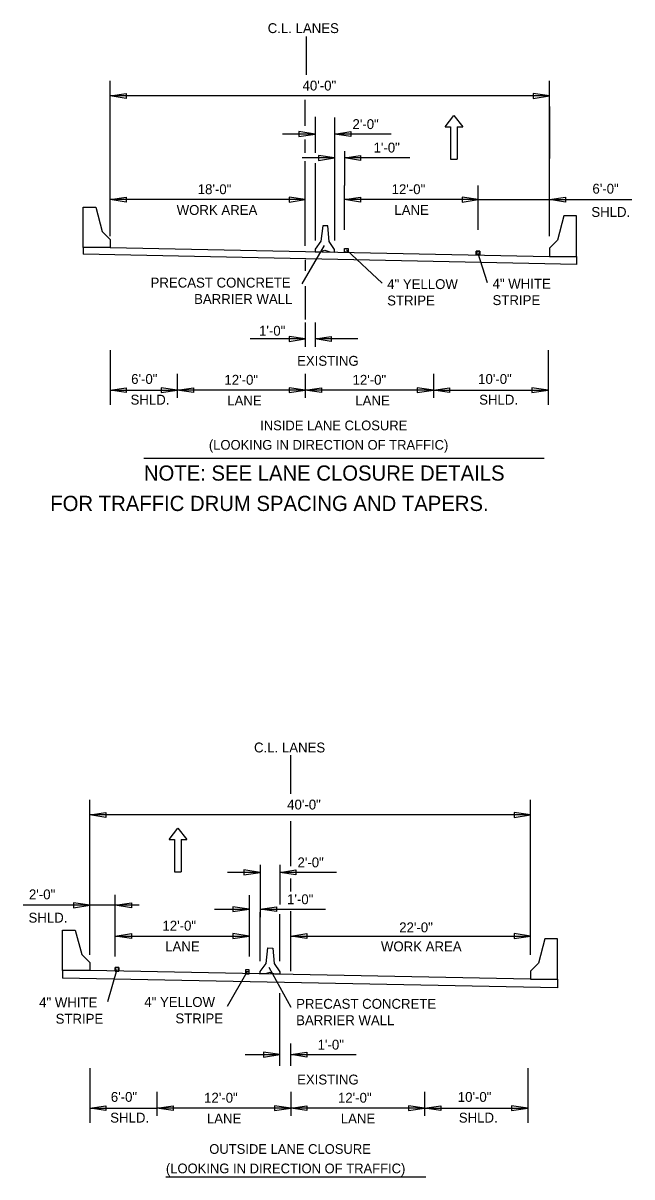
# Model space of a CAD drawing. Extents: x 13528 to 25043, y 7635 to 10612.
# Drawn here: x 24667 to 25043, y 9711 to 10423 of the extents above; entities that cross this region are included whole.
import ezdxf

# ---------------------------------------------------------------- set-up
doc = ezdxf.new("R2010")
doc.units = 0
for name, color, linetype in [('Default', 7, 'Continuous'), ('STAMP_PE_TAEGTMEYER-SIGNATURE', 7, 'Continuous'), ('STAMP_PRELIMINARY', 7, 'Continuous')]:
    doc.layers.add(name, color=color, linetype=linetype)

msp = doc.modelspace()

# ---------------------------------------------------------------- linework, layer by layer
at = {"layer": 'Default'}
for p, q in [((24841.84, 10391.32), (24841.84, 10415.16)), ((24720.38, 10291.82), (24720.38, 10387.65)), ((24991.93, 10291.82), (24991.93, 10387.65)), ((24991.93, 10378.33), (24720.38, 10378.33)), ((24841.04, 10359.8), (24841.04, 10376)), ((24991.93, 10371.84), (24991.93, 10339.74)), ((24847.12, 10365.43), (24847.12, 10343.14)), ((24859.18, 10365.07), (24859.18, 10332.97)), ((24847.12, 10354.79), (24826.95, 10354.79)), ((24841.04, 10343.26), (24841.04, 10351.36)), ((24894.21, 10354.79), (24859.18, 10354.79)), ((24865.21, 10344.18), (24865.21, 10323.08)), ((24859.18, 10340.02), (24839.02, 10340.02)), ((24841.04, 10324.57), (24841.04, 10337.97)), ((24847.12, 10336.78), (24847.12, 10305.87)), ((24905.59, 10340.02), (24865.21, 10340.02)), ((24859.18, 10332.97), (24859.18, 10288.96)), ((24841.04, 10285.69), (24841.04, 10324.57)), ((24865.21, 10295.57), (24865.21, 10323.08)), ((24947.95, 10295.57), (24947.95, 10323.08)), ((24841.04, 10314.31), (24720.38, 10314.31)), ((24947.95, 10314.31), (24865.21, 10314.31)), ((24947.95, 10314.31), (25042.91, 10314.31)), ((24847.12, 10305.87), (24847.12, 10288.96)), ((24839.18, 10262.21), (24852.93, 10285.86)), ((24865.21, 10281.75), (24865.21, 10284.04)), ((24865.21, 10284.04), (24867.51, 10284.04)), ((24865.21, 10281.75), (24865.21, 10284.04)), ((24865.21, 10284.04), (24867.51, 10284.04)), ((24867.51, 10281.75), (24865.21, 10281.75)), ((24888.49, 10262.67), (24866.4, 10283.19)), ((24867.51, 10284.04), (24867.51, 10281.75)), ((24867.51, 10284.04), (24867.51, 10281.75)), ((24948.92, 10282.42), (24946.62, 10282.42)), ((24946.62, 10282.42), (24946.62, 10280.12)), ((24946.62, 10280.12), (24946.62, 10282.42)), ((24946.62, 10282.42), (24948.92, 10282.42)), ((24948.92, 10280.12), (24946.62, 10280.12)), ((24953.62, 10262.9), (24947.77, 10281.55)), ((24948.92, 10280.12), (24948.92, 10282.42)), ((24948.92, 10282.42), (24948.92, 10280.12)), ((24841.04, 10277.11), (24841.04, 10270.29)), ((24841.04, 10260.9), (24841.04, 10240.29)), ((24841.04, 10238.38), (24841.04, 10223.42)), ((24847.07, 10238.38), (24847.07, 10223.42)), ((24841.04, 10228.22), (24806.88, 10228.22)), ((24873.44, 10228.22), (24847.07, 10228.22)), ((24720.38, 10221.33), (24720.38, 10187.46)), ((24991.14, 10221.33), (24991.14, 10187.46)), ((24720.38, 10206.74), (24720.38, 10191.78)), ((24761.88, 10206.74), (24761.88, 10191.78)), ((24841.04, 10206.74), (24841.04, 10191.78)), ((24920.2, 10206.74), (24920.2, 10191.78)), ((24720.38, 10196.58), (24761.88, 10196.58)), ((24841.04, 10196.58), (24761.88, 10196.58)), ((24920.2, 10196.58), (24841.04, 10196.58)), ((24920.2, 10196.58), (24991.14, 10196.58)), ((24741.33, 10154.6), (24988.59, 10154.6)), ((24832.05, 9947.17), (24832.05, 9971.01)), ((24707.81, 9847.68), (24707.81, 9943.51)), ((24980.16, 9847.68), (24980.16, 9943.51)), ((24980.16, 9934.18), (24707.81, 9934.18)), ((24832.05, 9902.56), (24832.05, 9930.28)), ((24813.15, 9903.43), (24813.15, 9871.02)), ((24825.21, 9903.43), (24825.21, 9878.94)), ((24813.15, 9898.71), (24792.98, 9898.71)), ((24860.24, 9898.71), (24825.21, 9898.71)), ((24832.05, 9886.93), (24832.05, 9894.85)), ((24723.57, 9846.66), (24723.57, 9884.83)), ((24806.3, 9884.72), (24806.3, 9846.66)), ((24738.35, 9878.37), (24666.6, 9878.37)), ((24784.95, 9875.95), (24806.3, 9875.95)), ((24813.14, 9875.95), (24853.48, 9875.95)), ((24813.14, 9843.86), (24813.14, 9874.18)), ((24825.21, 9843.86), (24825.21, 9872.93)), ((24832.05, 9847.85), (24832.05, 9874.69)), ((24723.57, 9859.37), (24806.3, 9859.37)), ((24832.05, 9859.37), (24980.16, 9859.37)), ((24832.05, 9837.77), (24832.05, 9847.85)), ((24718.91, 9818.98), (24724.71, 9838.88)), ((24723.57, 9837.74), (24723.57, 9840.03)), ((24723.57, 9840.03), (24725.86, 9840.03)), ((24725.86, 9840.03), (24723.57, 9840.03)), ((24723.57, 9840.03), (24723.57, 9837.74)), ((24723.57, 9837.74), (24725.86, 9837.74)), ((24725.86, 9840.03), (24725.86, 9837.74)), ((24725.86, 9837.74), (24725.86, 9840.03)), ((24792.92, 9816.05), (24805.16, 9837.28)), ((24804.01, 9838.43), (24804.01, 9836.13)), ((24806.3, 9838.43), (24804.01, 9838.43)), ((24804.01, 9838.43), (24804.01, 9836.13)), ((24806.3, 9837.28), (24804.01, 9837.28)), ((24806.3, 9836.13), (24806.3, 9838.43)), ((24806.3, 9836.13), (24806.3, 9838.43)), ((24832.22, 9815.19), (24818.79, 9839.88)), ((24804.01, 9836.13), (24806.3, 9836.13)), ((24825.21, 9779.25), (24825.21, 9824.16)), ((24832.05, 9779.25), (24832.05, 9793.01)), ((24803.86, 9786.13), (24825.21, 9786.13)), ((24832.05, 9786.13), (24872.38, 9786.13)), ((24707.81, 9777.82), (24707.81, 9743.95)), ((24978.56, 9777.82), (24978.56, 9743.95)), ((24707.81, 9763.23), (24707.81, 9748.27)), ((24749.31, 9763.23), (24749.31, 9748.27)), ((24832.05, 9763.23), (24832.05, 9748.27)), ((24914.79, 9763.23), (24914.79, 9748.27)), ((24707.81, 9753.07), (24749.31, 9753.07)), ((24832.05, 9753.07), (24749.31, 9753.07)), ((24914.79, 9753.07), (24832.05, 9753.07)), ((24914.79, 9753.07), (24978.56, 9753.07)), ((24754.87, 9710.57), (24915.46, 9710.57))]:
    msp.add_line(p, q, dxfattribs=at)
for points in [[(24720.38, 10378.33), (24730.38, 10379.83), (24730.38, 10376.83)], [(24991.93, 10378.33), (24981.93, 10379.83), (24981.93, 10376.83)], [(24847.12, 10354.79), (24837.12, 10356.29), (24837.12, 10353.29)], [(24859.18, 10354.79), (24869.18, 10356.29), (24869.18, 10353.29)], [(24859.18, 10340.02), (24849.18, 10341.52), (24849.18, 10338.52)], [(24865.21, 10340.02), (24875.21, 10341.52), (24875.21, 10338.52)], [(24720.38, 10314.31), (24730.38, 10315.81), (24730.38, 10312.81)], [(24841.04, 10314.31), (24831.04, 10315.81), (24831.04, 10312.81)], [(24865.21, 10314.31), (24875.21, 10315.81), (24875.21, 10312.81)], [(24947.95, 10314.31), (24937.95, 10315.81), (24937.95, 10312.81)], [(24991.93, 10314.31), (25001.93, 10315.81), (25001.93, 10312.81)], [(24841.04, 10228.22), (24831.04, 10229.72), (24831.04, 10226.72)], [(24847.07, 10228.22), (24857.07, 10229.72), (24857.07, 10226.72)], [(24720.38, 10196.58), (24730.38, 10198.08), (24730.38, 10195.08)], [(24761.88, 10196.58), (24751.88, 10198.08), (24751.88, 10195.08)], [(24761.88, 10196.58), (24771.88, 10198.08), (24771.88, 10195.08)], [(24841.04, 10196.58), (24831.04, 10198.08), (24831.04, 10195.08)], [(24841.04, 10196.58), (24851.04, 10198.08), (24851.04, 10195.08)], [(24920.2, 10196.58), (24910.2, 10198.08), (24910.2, 10195.08)], [(24920.2, 10196.58), (24930.2, 10198.08), (24930.2, 10195.08)], [(24991.14, 10196.58), (24981.14, 10198.08), (24981.14, 10195.08)], [(24707.81, 9934.18), (24717.81, 9935.68), (24717.81, 9932.68)], [(24980.16, 9934.18), (24970.16, 9935.68), (24970.16, 9932.68)], [(24813.15, 9898.71), (24803.15, 9900.21), (24803.15, 9897.21)], [(24825.21, 9898.71), (24835.21, 9900.21), (24835.21, 9897.21)], [(24707.81, 9878.37), (24697.81, 9879.87), (24697.81, 9876.87)], [(24723.57, 9878.37), (24733.57, 9879.87), (24733.57, 9876.87)], [(24806.3, 9875.95), (24796.3, 9877.45), (24796.3, 9874.45)], [(24813.14, 9875.95), (24823.14, 9877.45), (24823.14, 9874.45)], [(24723.57, 9859.37), (24733.57, 9860.87), (24733.57, 9857.87)], [(24806.3, 9859.37), (24796.3, 9860.87), (24796.3, 9857.87)], [(24832.05, 9859.37), (24842.05, 9860.87), (24842.05, 9857.87)], [(24980.16, 9859.37), (24970.16, 9860.87), (24970.16, 9857.87)], [(24825.21, 9786.13), (24815.21, 9787.63), (24815.21, 9784.63)], [(24832.05, 9786.13), (24842.05, 9787.63), (24842.05, 9784.63)], [(24707.81, 9753.07), (24717.81, 9754.57), (24717.81, 9751.57)], [(24749.31, 9753.07), (24759.31, 9754.57), (24759.31, 9751.57)], [(24832.05, 9753.07), (24822.05, 9754.57), (24822.05, 9751.57)], [(24832.05, 9753.07), (24842.05, 9754.57), (24842.05, 9751.57)], [(24914.79, 9753.07), (24904.79, 9754.57), (24904.79, 9751.57)], [(24914.79, 9753.07), (24924.79, 9754.57), (24924.79, 9751.57)], [(24978.56, 9753.07), (24968.56, 9754.57), (24968.56, 9751.57)]]:
    msp.add_lwpolyline(points, close=True, dxfattribs=at)
at = {"layer": 'STAMP_PE_TAEGTMEYER-SIGNATURE'}
for p, q in [((24927.46, 10359.21), (24932.88, 10366.25)), ((24932.88, 10366.25), (24938.31, 10359.21)), ((24927.46, 10359.21), (24930.85, 10359.21)), ((24930.85, 10359.21), (24930.85, 10339.27)), ((24934.92, 10359.21), (24934.92, 10339.27)), ((24934.92, 10359.21), (24938.31, 10359.21)), ((24930.85, 10339.27), (24934.92, 10339.27)), ((24756.87, 9918.94), (24762.3, 9925.98)), ((24762.3, 9925.98), (24767.72, 9918.94)), ((24756.87, 9918.94), (24760.26, 9918.94)), ((24760.26, 9918.94), (24760.26, 9899)), ((24764.33, 9918.94), (24764.33, 9899)), ((24764.33, 9918.94), (24767.72, 9918.94)), ((24760.26, 9899), (24764.33, 9899))]:
    msp.add_line(p, q, dxfattribs=at)
at = {"layer": 'STAMP_PRELIMINARY'}
for p, q in [((24851.93, 10298.13), (24850.74, 10288.6)), ((24854.95, 10298.07), (24851.93, 10298.13)), ((24855.76, 10288.5), (24854.95, 10298.07)), ((24850.74, 10288.6), (24847.12, 10283.64)), ((24859.18, 10283.4), (24855.76, 10288.5)), ((24703.7, 10284.67), (24703.7, 10280.59)), ((24720.48, 10284.67), (24703.7, 10284.67)), ((25008.62, 10274.14), (24703.7, 10280.59)), ((24720.48, 10284.67), (24991.93, 10279.24)), ((24847.12, 10283.64), (24847.07, 10282.14)), ((24847.07, 10282.14), (24850.09, 10282.08)), ((24850.09, 10282.08), (24853.12, 10283.02)), ((24853.12, 10283.02), (24856.12, 10281.96)), ((24856.12, 10281.96), (24859.13, 10281.9)), ((24859.13, 10281.9), (24859.18, 10283.4)), ((24991.93, 10279.24), (25008.72, 10279.24)), ((25008.72, 10279.23), (25008.72, 10274.14)), ((24816.78, 9842.5), (24817.97, 9852.03)), ((24817.97, 9852.03), (24820.99, 9851.97)), ((24820.99, 9851.97), (24821.8, 9842.4)), ((24691.05, 9838.07), (24691.05, 9833.42)), ((24707.84, 9838.07), (24691.05, 9838.07)), ((24980.19, 9832.65), (24707.84, 9838.07)), ((24813.15, 9836.04), (24813.16, 9837.55)), ((24813.16, 9837.55), (24816.78, 9842.5)), ((24819.2, 9836.92), (24816.16, 9835.98)), ((24822.19, 9835.86), (24819.2, 9836.92)), ((24821.8, 9842.4), (24825.22, 9837.3)), ((24825.22, 9837.3), (24825.21, 9835.8)), ((24996.95, 9827.45), (24691.05, 9833.42)), ((24816.16, 9835.98), (24813.15, 9836.04)), ((24825.21, 9835.8), (24822.19, 9835.86)), ((24980.2, 9832.65), (24996.99, 9832.65)), ((24996.98, 9832.64), (24996.98, 9827.45))]:
    msp.add_line(p, q, dxfattribs=at)
for points in [[(24703.7, 10284.66), (24703.7, 10309.66), (24711.52, 10309.66), (24715.49, 10294.66)], [(25008.72, 10279.23), (25008.72, 10304.23), (25000.89, 10304.23), (24996.92, 10289.23)], [(24715.49, 10294.66), (24720.49, 10289.66), (24720.48, 10284.67)], [(24996.92, 10289.23), (24991.92, 10284.23), (24991.93, 10279.24)], [(24691.05, 9838.07), (24691.05, 9863.07), (24698.88, 9863.07), (24702.85, 9848.07)], [(24996.99, 9832.64), (24996.99, 9857.64), (24989.16, 9857.64), (24985.19, 9842.64)], [(24702.85, 9848.07), (24707.85, 9843.07), (24707.84, 9838.07)], [(24985.19, 9842.64), (24980.19, 9837.64), (24980.2, 9832.65)]]:
    msp.add_lwpolyline(points, dxfattribs=at)

# ---------------------------------------------------------------- texts
at = {"layer": 'Default'}
for s, height, p in [('C.L. LANES', 6.1, (24817.81, 10417.17)), ('40\'-0"', 6.1, (24839.35, 10381.69)), ('2\'-0"', 6.1, (24870.2, 10357.89)), ('1\'-0"', 6.1, (24883.22, 10343.38)), ('18\'-0"', 6.1, (24774.56, 10317.67)), ('12\'-0"', 6.1, (24894.4, 10317.67)), ('6\'-0"', 6.1, (25018.51, 10318)), ('WORK AREA', 6.1, (24761.54, 10304.85)), ('LANE', 6.1, (24896.11, 10304.85)), ('SHLD.', 6.1, (25017.82, 10303.61)), ('PRECAST CONCRETE', 6.1, (24745.41, 10259.98)), ('4" YELLOW', 6.1, (24891.65, 10259.05)), ('4" WHITE', 6.1, (24956.77, 10259.28)), ('BARRIER WALL', 6.1, (24772.32, 10249.85)), ('STRIPE', 6.1, (24891.65, 10248.92)), ('STRIPE', 6.1, (24956.77, 10249.15)), ('1\'-0"', 6.1, (24812.46, 10230.25)), ('EXISTING', 6.1, (24835.97, 10211.66)), ('6\'-0"', 6.1, (24733.41, 10200.45)), ('12\'-0"', 6.1, (24791.07, 10199.94)), ('12\'-0"', 6.1, (24870.23, 10199.94)), ('10\'-0"', 6.1, (24947.86, 10200.45)), ('SHLD.', 6.1, (24733.04, 10187.65)), ('LANE', 6.1, (24792.78, 10187.12)), ('LANE', 6.1, (24871.94, 10187.12)), ('SHLD.', 6.1, (24948.5, 10187.65)), ('INSIDE LANE CLOSURE', 6, (24813.15, 10171.81)), ('(LOOKING IN DIRECTION OF TRAFFIC)', 6, (24781.45, 10159.81)), ('NOTE: SEE LANE CLOSURE DETAILS ', 9.375, (24741.26, 10140.7)), ('FOR TRAFFIC DRUM SPACING AND TAPERS.', 9.375, (24683.41, 10121.95)), ('C.L. LANES', 6.1, (24809.36, 9972.8)), ('40\'-0"', 6.1, (24829.84, 9937.54)), ('2\'-0"', 6.1, (24836.22, 9901.82)), ('2\'-0"', 6.1, (24670.25, 9882.06)), ('1\'-0"', 6.1, (24829.77, 9879.05)), ('SHLD.', 6.1, (24669.98, 9867.67)), ('12\'-0"', 6.1, (24752.75, 9862.73)), ('22\'-0"', 6.1, (24899.09, 9861.68)), ('LANE', 6.1, (24754.46, 9849.91)), ('WORK AREA', 6.1, (24887.8, 9849.91)), ('4" WHITE', 6.1, (24676.55, 9815.35)), ('4" YELLOW', 6.1, (24741.53, 9815.58)), ('PRECAST CONCRETE', 6.1, (24835.38, 9814.44)), ('STRIPE', 6.1, (24686.74, 9805.23)), ('STRIPE', 6.1, (24760.75, 9805.46)), ('BARRIER WALL', 6.1, (24835.38, 9804.31)), ('1\'-0"', 6.1, (24848.67, 9789.23)), ('EXISTING', 6.1, (24835.97, 9767.68)), ('6\'-0"', 6.1, (24720.84, 9756.94)), ('12\'-0"', 6.1, (24778.5, 9756.43)), ('12\'-0"', 6.1, (24861.24, 9756.43)), ('10\'-0"', 6.1, (24935.29, 9756.94)), ('SHLD.', 6.1, (24720.47, 9744.14)), ('LANE', 6.1, (24780.21, 9743.61)), ('LANE', 6.1, (24862.95, 9743.61)), ('SHLD.', 6.1, (24935.93, 9744.14)), ('OUTSIDE LANE CLOSURE', 6, (24781.68, 9724.83)), ('(LOOKING IN DIRECTION OF TRAFFIC)', 6, (24754.9, 9712.83))]:
    msp.add_text(s, height=height, dxfattribs=at).set_placement(p)

doc.saveas('drawing.dxf')
